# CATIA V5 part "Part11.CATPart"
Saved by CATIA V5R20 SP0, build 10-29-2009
Part number: 1bola238
Revision: ANY
Definition: UNKNOWN
Nomenclature: 1bola238
Source: Unknown
Bounding box of the stored display mesh (mm): x -1.19 to 1.19, y -1.19 to 1.19, z -1.19 to 1.19
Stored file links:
  C:\Users\Utente\Desktop\IO LAVORO\3D X SITO CF\CUMSA\3D files BA\BA 101822\Part11.CATPart
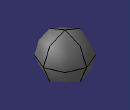
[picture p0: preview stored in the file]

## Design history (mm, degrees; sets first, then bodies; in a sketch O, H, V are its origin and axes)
Body1 "Revolución1" (main body)
  Solid1: solid without history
